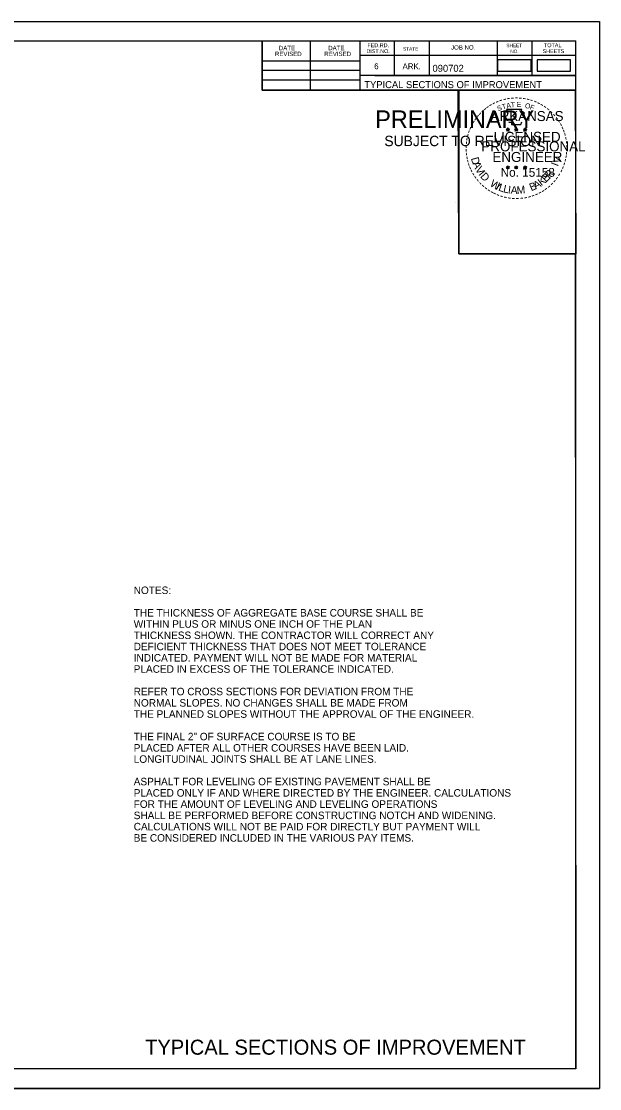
# Model space of a CAD drawing. Extents: x 1371763 to 1372860, y 385599 to 385872.
# Drawn here: x 1372801.9 to 1372859.7, y 385598.6 to 385705.3 of the extents above; entities that cross this region are included whole.
import ezdxf

# ---------------------------------------------------------------- set-up
doc = ezdxf.new("R2010")
doc.units = 0
for name, color, linetype in [('R_Border', 7, 'Continuous'), ('R_Border PE', 7, 'Continuous'), ('R_Border Prem', 7, 'Continuous'), ('R_Dimension', 7, 'Continuous'), ('R_Draft', 7, 'Continuous'), ('R_No Plot', 7, 'Continuous')]:
    doc.layers.add(name, color=color, linetype=linetype)

msp = doc.modelspace()

# ---------------------------------------------------------------- linework, layer by layer
at = {"layer": 'R_Border'}
for p, q in [((1372699.21, 385703.31), (1372857.3, 385703.31)), ((1372825.98, 385698.37), (1372825.98, 385703.31)), ((1372830.82, 385698.37), (1372830.82, 385703.31)), ((1372835.75, 385703.31), (1372835.75, 385698.37)), ((1372839.17, 385703.31), (1372839.17, 385699.84)), ((1372842.64, 385703.31), (1372842.64, 385699.84)), ((1372849.43, 385703.31), (1372849.43, 385699.84)), ((1372852.9, 385703.31), (1372852.9, 385699.84)), ((1372857.3, 385600.58), (1372857.3, 385703.31)), ((1372857.3, 385701.84), (1372835.75, 385701.84)), ((1372857.3, 385701.85), (1372857.3, 385701.85)), ((1372825.98, 385701.3), (1372835.75, 385701.3)), ((1372825.98, 385700.37), (1372835.75, 385700.37)), ((1372857.3, 385699.84), (1372835.75, 385699.84)), ((1372837.23, 385699.84), (1372857.3, 385699.84)), ((1372825.98, 385699.4), (1372835.75, 385699.4)), ((1372857.3, 385698.37), (1372825.98, 385698.37)), ((1372857.3, 385600.58), (1372699.21, 385600.58))]:
    msp.add_line(p, q, dxfattribs=at)
at = {"layer": 'R_Border PE'}
for p, q in [((1372850.34, 385694.49), (1372850.51, 385694.44)), ((1372850.34, 385694.49), (1372850.47, 385694.47)), ((1372850.34, 385694.49), (1372850.46, 385694.43)), ((1372850.41, 385694.29), (1372850.51, 385694.44)), ((1372850.41, 385694.29), (1372850.47, 385694.41)), ((1372850.41, 385694.29), (1372850.51, 385694.4)), ((1372850.51, 385694.62), (1372850.49, 385694.5)), ((1372850.51, 385694.44), (1372850.51, 385694.62)), ((1372850.51, 385694.62), (1372850.54, 385694.5)), ((1372850.69, 385694.49), (1372850.51, 385694.44)), ((1372850.62, 385694.29), (1372850.51, 385694.44)), ((1372850.62, 385694.29), (1372850.51, 385694.4)), ((1372850.69, 385694.49), (1372850.55, 385694.47)), ((1372850.62, 385694.29), (1372850.55, 385694.44)), ((1372850.69, 385694.49), (1372850.59, 385694.44)), ((1372851.18, 385694.49), (1372851.35, 385694.44)), ((1372851.18, 385694.49), (1372851.3, 385694.47)), ((1372851.18, 385694.49), (1372851.29, 385694.43)), ((1372851.24, 385694.29), (1372851.35, 385694.44)), ((1372851.24, 385694.29), (1372851.3, 385694.41)), ((1372851.24, 385694.29), (1372851.35, 385694.4)), ((1372851.35, 385694.62), (1372851.33, 385694.5)), ((1372851.35, 385694.44), (1372851.35, 385694.62)), ((1372851.35, 385694.62), (1372851.37, 385694.5)), ((1372851.52, 385694.49), (1372851.35, 385694.44)), ((1372851.46, 385694.29), (1372851.35, 385694.44)), ((1372851.46, 385694.29), (1372851.35, 385694.4)), ((1372851.52, 385694.49), (1372851.38, 385694.47)), ((1372851.46, 385694.29), (1372851.39, 385694.44)), ((1372851.52, 385694.49), (1372851.42, 385694.44)), ((1372852.06, 385694.49), (1372852.23, 385694.43)), ((1372852.06, 385694.49), (1372852.18, 385694.47)), ((1372852.06, 385694.49), (1372852.18, 385694.43)), ((1372852.12, 385694.28), (1372852.23, 385694.43)), ((1372852.12, 385694.28), (1372852.19, 385694.41)), ((1372852.12, 385694.28), (1372852.23, 385694.39)), ((1372852.23, 385694.62), (1372852.21, 385694.49)), ((1372852.23, 385694.43), (1372852.23, 385694.62)), ((1372852.23, 385694.62), (1372852.26, 385694.49)), ((1372852.41, 385694.49), (1372852.23, 385694.43)), ((1372852.34, 385694.28), (1372852.23, 385694.43)), ((1372852.34, 385694.28), (1372852.23, 385694.39)), ((1372852.41, 385694.49), (1372852.26, 385694.46)), ((1372852.34, 385694.28), (1372852.27, 385694.43)), ((1372852.41, 385694.49), (1372852.3, 385694.44)), ((1372850.34, 385690.71), (1372850.51, 385690.65)), ((1372850.34, 385690.71), (1372850.46, 385690.69)), ((1372850.34, 385690.71), (1372850.46, 385690.65)), ((1372850.4, 385690.5), (1372850.51, 385690.65)), ((1372850.4, 385690.5), (1372850.47, 385690.63)), ((1372850.4, 385690.5), (1372850.51, 385690.61)), ((1372850.51, 385690.83), (1372850.49, 385690.71)), ((1372850.51, 385690.65), (1372850.51, 385690.83)), ((1372850.51, 385690.83), (1372850.54, 385690.71)), ((1372850.69, 385690.71), (1372850.51, 385690.65)), ((1372850.62, 385690.5), (1372850.51, 385690.65)), ((1372850.62, 385690.5), (1372850.51, 385690.61)), ((1372850.69, 385690.71), (1372850.54, 385690.68)), ((1372850.62, 385690.5), (1372850.55, 385690.65)), ((1372850.69, 385690.71), (1372850.58, 385690.66)), ((1372851.17, 385690.71), (1372851.35, 385690.65)), ((1372851.17, 385690.71), (1372851.3, 385690.69)), ((1372851.17, 385690.71), (1372851.29, 385690.65)), ((1372851.24, 385690.5), (1372851.35, 385690.65)), ((1372851.24, 385690.5), (1372851.3, 385690.63)), ((1372851.24, 385690.5), (1372851.35, 385690.61)), ((1372851.35, 385690.83), (1372851.33, 385690.71)), ((1372851.35, 385690.65), (1372851.35, 385690.83)), ((1372851.35, 385690.83), (1372851.37, 385690.71)), ((1372851.52, 385690.71), (1372851.35, 385690.65)), ((1372851.45, 385690.5), (1372851.35, 385690.65)), ((1372851.45, 385690.5), (1372851.35, 385690.61)), ((1372851.52, 385690.71), (1372851.38, 385690.68)), ((1372851.45, 385690.5), (1372851.39, 385690.65)), ((1372851.52, 385690.71), (1372851.42, 385690.66)), ((1372852.06, 385690.7), (1372852.23, 385690.65)), ((1372852.06, 385690.7), (1372852.18, 385690.68)), ((1372852.06, 385690.7), (1372852.17, 385690.64)), ((1372852.12, 385690.5), (1372852.23, 385690.65)), ((1372852.12, 385690.5), (1372852.19, 385690.62)), ((1372852.12, 385690.5), (1372852.23, 385690.61)), ((1372852.23, 385690.83), (1372852.21, 385690.7)), ((1372852.23, 385690.65), (1372852.23, 385690.83)), ((1372852.23, 385690.83), (1372852.26, 385690.7)), ((1372852.4, 385690.7), (1372852.23, 385690.65)), ((1372852.34, 385690.5), (1372852.23, 385690.65)), ((1372852.34, 385690.5), (1372852.23, 385690.61)), ((1372852.4, 385690.7), (1372852.26, 385690.68)), ((1372852.34, 385690.5), (1372852.27, 385690.64)), ((1372852.4, 385690.7), (1372852.3, 385690.65))]:
    msp.add_line(p, q, dxfattribs=at)
for points in [[(1372850.36, 385696.43), (1372850.5, 385696.02)], [(1372852.12, 385695.97), (1372852.19, 385696.11), (1372851.84, 385696.1), (1372851.92, 385696.43), (1372850.36, 385696.43)], [(1372850.61, 385695.22), (1372850.61, 385695.18), (1372850.89, 385695.17), (1372850.86, 385694.93), (1372851.8, 385694.93), (1372851.9, 385695.2)], [(1372850.51, 385694.62), (1372850.62, 385694.29), (1372850.34, 385694.49), (1372850.69, 385694.49), (1372850.41, 385694.29), (1372850.51, 385694.62)], [(1372851.35, 385694.62), (1372851.46, 385694.29), (1372851.18, 385694.49), (1372851.52, 385694.49), (1372851.24, 385694.29), (1372851.35, 385694.62)], [(1372852.23, 385694.62), (1372852.34, 385694.28), (1372852.06, 385694.49), (1372852.41, 385694.49), (1372852.12, 385694.28), (1372852.23, 385694.62)], [(1372850.51, 385690.83), (1372850.62, 385690.5), (1372850.34, 385690.71), (1372850.69, 385690.71), (1372850.4, 385690.5), (1372850.51, 385690.83)], [(1372851.35, 385690.83), (1372851.45, 385690.5), (1372851.17, 385690.71), (1372851.52, 385690.71), (1372851.24, 385690.5), (1372851.35, 385690.83)], [(1372852.23, 385690.83), (1372852.34, 385690.5), (1372852.06, 385690.7), (1372852.4, 385690.7), (1372852.12, 385690.5), (1372852.23, 385690.83)]]:
    msp.add_lwpolyline(points, dxfattribs=at)
for centre, radius in [((1372850.51, 385694.44), 0.0861), ((1372850.51, 385694.44), 0.0723), ((1372850.51, 385694.44), 0.0579), ((1372850.51, 385694.44), 0.0495), ((1372850.51, 385694.44), 0.0374), ((1372850.51, 385694.44), 0.0248), ((1372850.51, 385694.44), 0.0148), ((1372851.35, 385694.44), 0.0861), ((1372851.35, 385694.44), 0.0723), ((1372851.35, 385694.44), 0.0579), ((1372851.35, 385694.44), 0.0495), ((1372851.35, 385694.44), 0.0374), ((1372851.35, 385694.44), 0.0248), ((1372851.35, 385694.44), 0.0148), ((1372852.23, 385694.43), 0.0861), ((1372852.23, 385694.43), 0.0723), ((1372852.23, 385694.43), 0.0579), ((1372852.23, 385694.43), 0.0495), ((1372852.23, 385694.43), 0.0374), ((1372852.23, 385694.43), 0.0248), ((1372852.23, 385694.43), 0.0148), ((1372850.51, 385690.65), 0.0861), ((1372850.51, 385690.65), 0.0723), ((1372850.51, 385690.65), 0.0579), ((1372850.51, 385690.65), 0.0495), ((1372850.51, 385690.65), 0.0374), ((1372850.51, 385690.65), 0.0248), ((1372850.51, 385690.65), 0.0148), ((1372851.35, 385690.65), 0.0861), ((1372851.35, 385690.65), 0.0723), ((1372851.35, 385690.65), 0.0579), ((1372851.35, 385690.65), 0.0495), ((1372851.35, 385690.65), 0.0374), ((1372851.35, 385690.65), 0.0248), ((1372851.35, 385690.65), 0.0148), ((1372852.23, 385690.65), 0.0861), ((1372852.23, 385690.65), 0.0723), ((1372852.23, 385690.65), 0.0579), ((1372852.23, 385690.65), 0.0495), ((1372852.23, 385690.65), 0.0374), ((1372852.23, 385690.65), 0.0248), ((1372852.23, 385690.65), 0.0148)]:
    msp.add_circle(centre, radius, dxfattribs=at)
at = {"layer": 'R_Draft'}
for points in [[(1372849.49, 385700.26), (1372852.83, 385700.26), (1372852.83, 385701.41), (1372849.49, 385701.41)], [(1372853.43, 385700.26), (1372856.77, 385700.26), (1372856.77, 385701.41), (1372853.43, 385701.41)]]:
    msp.add_lwpolyline(points, close=True, dxfattribs=at)
at = {"layer": 'R_No Plot'}
for p, q in [((1372693.01, 385705.25), (1372859.67, 385705.25)), ((1372845.31, 385687.14), (1372845.31, 385687.14)), ((1372693.01, 385598.59), (1372859.67, 385598.59))]:
    msp.add_line(p, q, dxfattribs=at)
for points in [[(1372693, 385705.25), (1372859.67, 385705.25), (1372859.67, 385598.59), (1372693, 385598.59)], [(1372816.17, 385703.31), (1372825.98, 385703.31), (1372825.98, 385698.37), (1372834.03, 385698.37), (1372845.63, 385698.37), (1372845.63, 385682.03), (1372857.24, 385682.03), (1372857.3, 385600.58), (1372699.21, 385600.58), (1372699.21, 385703.31)], [(1372845.56, 385698.37), (1372857.24, 385698.37), (1372857.31, 385682.03), (1372845.63, 385682.03)]]:
    msp.add_lwpolyline(points, close=True, dxfattribs=at)

# ---------------------------------------------------------------- texts
at = {"layer": 'R_Border'}
for s, height, p in [('DATE', 0.44, (1372827.65, 385702.37)), ('DATE', 0.44, (1372832.58, 385702.37)), ('FED.RD.', 0.391, (1372836.49, 385702.67)), ('STATE', 0.342, (1372840.05, 385702.33)), ('JOB NO.', 0.44, (1372844.84, 385702.43)), ('SHEET', 0.342, (1372850.36, 385702.67)), ('TOTAL', 0.391, (1372854.12, 385702.67)), ('REVISED', 0.44, (1372827.26, 385701.78)), ('REVISED', 0.44, (1372832.19, 385701.78)), ('DIST.NO.', 0.391, (1372836.39, 385702.08)), ('NO.', 0.342, (1372850.75, 385702.08)), ('SHEETS', 0.391, (1372853.98, 385702.08)), ('6', 0.586, (1372837.17, 385700.47)), ('ARK.', 0.586, (1372840, 385700.47)), ('090702', 0.7, (1372842.99, 385700.21)), ('TYPICAL SECTIONS OF IMPROVEMENT', 0.7, (1372836.18, 385698.58))]:
    msp.add_text(s, height=height, dxfattribs=at).set_placement(p)
at = {"layer": 'R_Border PE'}
for s, height, rotation, p in [('-', 0.8, 19.1761, (1372849.73, 385697)), ('-', 0.8, 13.6302, (1372850.11, 385697.12)), ('-', 0.8, 10.2193, (1372850.45, 385697.2)), ('-', 0.8, 5.8968, (1372850.81, 385697.25)), ('-', 0.8, 0.1862, (1372851.2, 385697.29)), ('-', 0.8, 357.743, (1372851.56, 385697.28)), ('-', 0.8, 352.1617, (1372851.93, 385697.25)), ('-', 0.8, 347.2049, (1372852.29, 385697.2)), ('-', 0.8, 342.3362, (1372852.61, 385697.12)), ('-', 0.8, 337.8551, (1372852.98, 385697.01)), ('-', 0.8, 42.9622, (1372848.06, 385695.92)), ('-', 0.8, 38.9507, (1372848.28, 385696.13)), ('-', 0.8, 36.2317, (1372848.51, 385696.32)), ('-', 0.8, 34.0636, (1372848.8, 385696.52)), ('-', 0.8, 28.7918, (1372849.1, 385696.7)), ('-', 0.8, 24.3072, (1372849.42, 385696.86)), ('S', 0.5, 21.594, (1372849.54, 385696.27)), ('T', 0.5, 16.4036, (1372850, 385696.44)), ('A', 0.5, 11.2132, (1372850.41, 385696.56)), ('T', 0.5, 6.0228, (1372850.83, 385696.65)), ('E', 0.5, 0.8323, (1372851.39, 385696.7)), ('O', 0.5, 350.4515, (1372852.19, 385696.6)), ('F', 0.5, 340.0707, (1372852.66, 385696.48)), ('-', 0.8, 334.1211, (1372853.29, 385696.87)), ('-', 0.8, 329.6409, (1372853.58, 385696.73)), ('-', 0.8, 325.8627, (1372853.9, 385696.55)), ('-', 0.8, 320.5297, (1372854.21, 385696.34)), ('-', 0.8, 315.5786, (1372854.51, 385696.09)), ('-', 0.8, 58.0706, (1372847.26, 385694.89)), ('-', 0.8, 54.2325, (1372847.43, 385695.16)), ('-', 0.8, 50.6142, (1372847.63, 385695.44)), ('-', 0.8, 48.4231, (1372847.84, 385695.68)), ('-', 0.8, 309.8797, (1372854.79, 385695.82)), ('-', 0.8, 306.6522, (1372855.06, 385695.52)), ('-', 0.7, 303.6753, (1372855.3, 385695.23)), ('-', 0.8, 72.3945, (1372846.87, 385693.97)), ('-', 0.8, 67.7743, (1372846.98, 385694.28)), ('-', 0.8, 62.8713, (1372847.11, 385694.59)), ('-', 0.8, 299.6684, (1372855.46, 385694.93)), ('-', 0.8, 294.6628, (1372855.62, 385694.62)), ('-', 0.8, 290.5728, (1372855.75, 385694.34)), ('-', 0.8, 85.1863, (1372846.67, 385692.91)), ('-', 0.8, 81.2013, (1372846.7, 385693.25)), ('-', 0.8, 75.461, (1372846.77, 385693.61)), ('-', 0.8, 285.1233, (1372855.87, 385694.05)), ('-', 0.8, 280.5493, (1372855.97, 385693.68)), ('-', 0.8, 276.5962, (1372856.05, 385693.29)), ('-', 0.8, 89.0622, (1372846.65, 385692.56)), ('-', 0.8, 94.1959, (1372846.67, 385692.2)), ('-', 0.8, 98.9479, (1372846.71, 385691.86)), ('-', 0.8, 263.5172, (1372856.08, 385692.28)), ('-', 0.8, 274.3301, (1372856.08, 385692.93)), ('-', 0.8, 269.9407, (1372856.09, 385692.61)), ('-', 0.8, 101.7149, (1372846.78, 385691.5)), ('-', 0.8, 105.4578, (1372846.86, 385691.2)), ('-', 0.8, 109.0874, (1372846.96, 385690.88)), ('D', 0.77, 286.2848, (1372846.82, 385691.56)), ('A', 0.77, 292.7835, (1372846.97, 385691.06)), ('I', 0.77, 69.0301, (1372855.5, 385690.71)), ('V', 0.77, 72.6573, (1372855.62, 385690.98)), ('-', 0.8, 252.8681, (1372855.9, 385691.26)), ('-', 0.8, 255.7626, (1372855.99, 385691.62)), ('-', 0.8, 260.9953, (1372856.05, 385691.95)), ('-', 0.8, 114.0643, (1372847.09, 385690.58)), ('-', 0.8, 115.7289, (1372847.24, 385690.28)), ('-', 0.8, 120.4471, (1372847.42, 385689.98)), ('V', 0.77, 300.7936, (1372847.22, 385690.47)), ('I', 0.77, 308.3502, (1372847.54, 385689.96)), ('D', 0.77, 311.9774, (1372847.71, 385689.72)), ('E', 0.77, 44.0175, (1372854.31, 385689.12)), ('R', 0.77, 50.3651, (1372854.68, 385689.47)), (',', 0.77, 57.4684, (1372855.04, 385689.91)), ('-', 0.8, 239.0712, (1372855.46, 385690.23)), ('-', 0.8, 244.6197, (1372855.66, 385690.6)), ('-', 0.8, 247.8887, (1372855.79, 385690.92)), ('-', 0.8, 125.8934, (1372847.62, 385689.7)), ('-', 0.8, 130.7181, (1372847.85, 385689.43)), ('-', 0.8, 134.2238, (1372848.11, 385689.15)), ('-', 0.8, 138.9338, (1372848.38, 385688.92)), ('W', 0.77, 328.0731, (1372848.65, 385688.84)), ('I', 0.77, 336.6877, (1372849.25, 385688.48)), ('L', 0.77, 340.3149, (1372849.51, 385688.36)), ('L', 0.77, 346.6625, (1372849.99, 385688.19)), ('I', 0.77, 353.0101, (1372850.49, 385688.07)), ('A', 0.77, 356.6373, (1372850.78, 385688.03)), ('M', 0.77, 4.6473, (1372851.42, 385688)), ('B', 0.77, 22.8589, (1372852.85, 385688.27)), ('A', 0.77, 28.9042, (1372853.3, 385688.45)), ('K', 0.77, 36.9143, (1372853.86, 385688.77)), ('-', 0.8, 221.0851, (1372854.55, 385689.08)), ('-', 0.8, 225.7653, (1372854.81, 385689.34)), ('-', 0.8, 231.2538, (1372855.05, 385689.62)), ('-', 0.8, 233.8452, (1372855.26, 385689.9)), ('-', 0.8, 144.6463, (1372848.65, 385688.72)), ('-', 0.8, 148.0898, (1372848.93, 385688.53)), ('-', 0.8, 151.5704, (1372849.22, 385688.37)), ('-', 0.8, 154.6002, (1372849.48, 385688.25)), ('-', 0.8, 158.5612, (1372849.8, 385688.12)), ('-', 0.8, 162.7983, (1372850.14, 385688.01)), ('-', 0.8, 167.5555, (1372850.5, 385687.93)), ('-', 0.8, 195.4743, (1372852.77, 385688.06)), ('-', 0.8, 199.4643, (1372853.1, 385688.18)), ('-', 0.8, 204.2516, (1372853.41, 385688.32)), ('-', 0.8, 207.3568, (1372853.73, 385688.48)), ('-', 0.8, 212.2491, (1372854.01, 385688.65)), ('-', 0.8, 215.7363, (1372854.27, 385688.85)), ('-', 0.8, 173.1155, (1372850.88, 385687.88)), ('-', 0.8, 176.5183, (1372851.26, 385687.85)), ('-', 0.8, 181.5918, (1372851.63, 385687.86)), ('-', 0.8, 185.8167, (1372852.03, 385687.9)), ('-', 0.8, 191.2858, (1372852.4, 385687.96))]:
    msp.add_text(s, height=height, rotation=rotation, dxfattribs=at).set_placement(p)
for s, height, p in [('ARKANSAS', 1, (1372848.79, 385695.29)), ('LICENSED', 1, (1372849.09, 385693.21)), ('PROFESSIONAL', 1, (1372847.87, 385692.26)), ('ENGINEER', 1, (1372848.97, 385691.2)), ('No. 15158', 0.878, (1372849.79, 385689.72)), ('AAMU', 0.00001, (1372851.31, 385688))]:
    msp.add_text(s, height=height, dxfattribs=at).set_placement(p)
at = {"layer": 'R_Border Prem'}
for s, height, p in [('PRELIMINARY', 1.75, (1372837.27, 385694.6)), ('DWB', 0.005, (1372837.65, 385695.52)), ('SUBJECT TO REVISION', 1.0376, (1372838.18, 385692.78))]:
    msp.add_text(s, height=height, dxfattribs=at).set_placement(p)
at = {"layer": 'R_Dimension'}
msp.add_text('TYPICAL SECTIONS OF IMPROVEMENT', height=1.5, dxfattribs=at).set_placement((1372814.3, 385601.98))
at = {"layer": 'R_Draft'}
for s, p in [('NOTES:', (1372813.16, 385648.02)), ('THE THICKNESS OF AGGREGATE BASE COURSE SHALL BE', (1372813.16, 385645.77)), ('WITHIN PLUS OR MINUS ONE INCH OF THE PLAN', (1372813.16, 385644.65)), ('THICKNESS SHOWN. THE CONTRACTOR WILL CORRECT ANY', (1372813.16, 385643.52)), ('DEFICIENT THICKNESS THAT DOES NOT MEET TOLERANCE ', (1372813.16, 385642.4)), ('INDICATED. PAYMENT WILL NOT BE MADE FOR MATERIAL', (1372813.16, 385641.27)), ('PLACED IN EXCESS OF THE TOLERANCE INDICATED.', (1372813.16, 385640.15)), ('REFER TO CROSS SECTIONS FOR DEVIATION FROM THE', (1372813.16, 385637.9)), ('NORMAL SLOPES. NO CHANGES SHALL BE MADE FROM', (1372813.16, 385636.77)), ('THE PLANNED SLOPES WITHOUT THE APPROVAL OF THE ENGINEER.', (1372813.16, 385635.65)), ('THE FINAL 2" OF SURFACE COURSE IS TO BE', (1372813.16, 385633.4)), ('PLACED AFTER ALL OTHER COURSES HAVE BEEN LAID.', (1372813.16, 385632.27)), ('LONGITUDINAL JOINTS SHALL BE AT LANE LINES.', (1372813.16, 385631.15)), ('ASPHALT FOR LEVELING OF EXISTING PAVEMENT SHALL BE', (1372813.16, 385628.9)), ('PLACED ONLY IF AND WHERE DIRECTED BY THE ENGINEER. CALCULATIONS', (1372813.16, 385627.77)), ('FOR THE AMOUNT OF LEVELING AND LEVELING OPERATIONS', (1372813.16, 385626.65)), ('SHALL BE PERFORMED BEFORE CONSTRUCTING NOTCH AND WIDENING.', (1372813.16, 385625.52)), ('CALCULATIONS WILL NOT BE PAID FOR DIRECTLY BUT PAYMENT WILL', (1372813.16, 385624.4)), ('BE CONSIDERED INCLUDED IN THE VARIOUS PAY ITEMS.', (1372813.16, 385623.27))]:
    msp.add_text(s, height=0.75, dxfattribs=at).set_placement(p)

doc.saveas('drawing.dxf')
